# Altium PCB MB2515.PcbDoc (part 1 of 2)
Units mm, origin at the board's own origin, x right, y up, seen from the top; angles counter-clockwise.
Board outline 43 x 51.45 mm, 4 copper layers (Top Layer, Internal 1, Internal 2, Bottom Layer), stack 1.565 mm thick; 100 components, 89 nets, 374 pads, 852 vias.
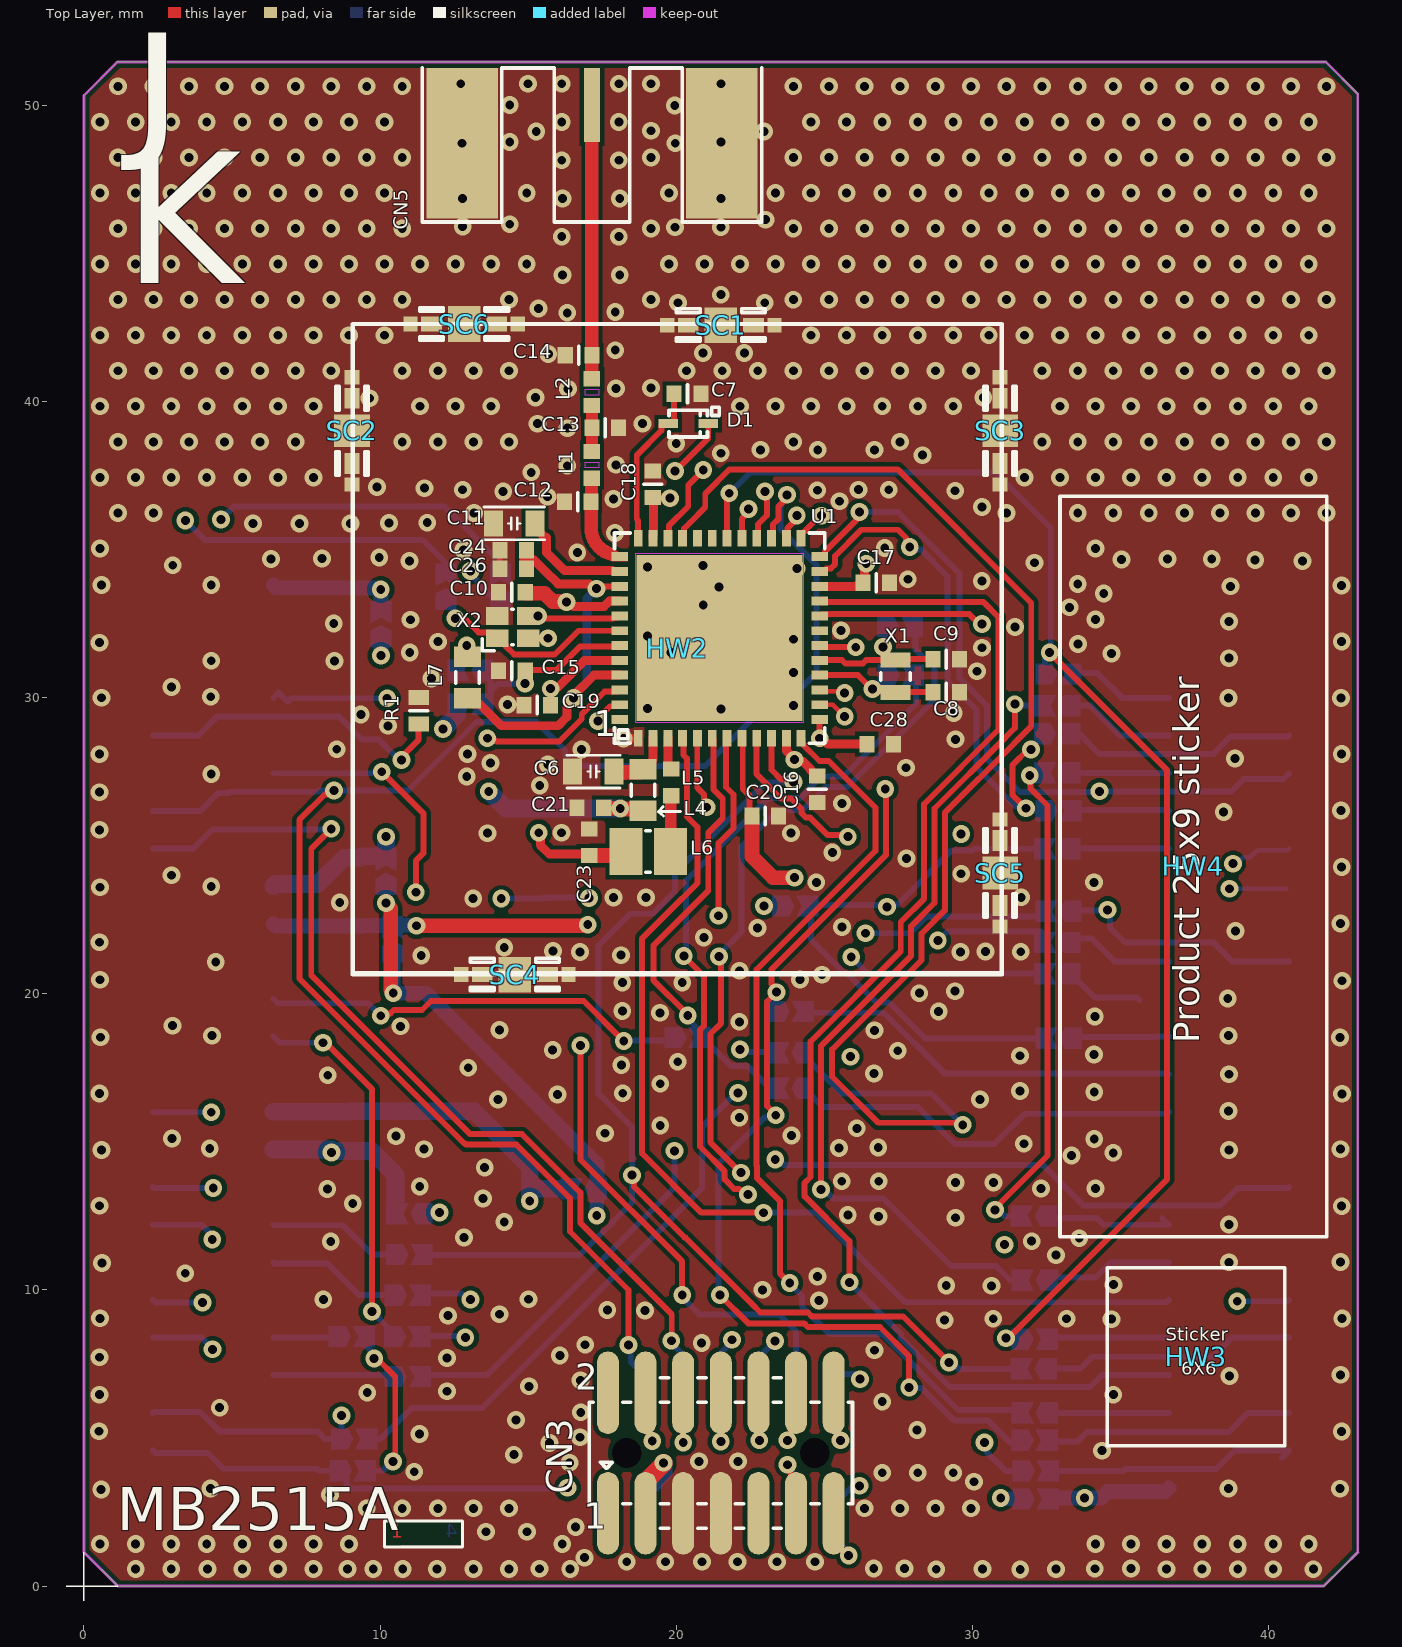
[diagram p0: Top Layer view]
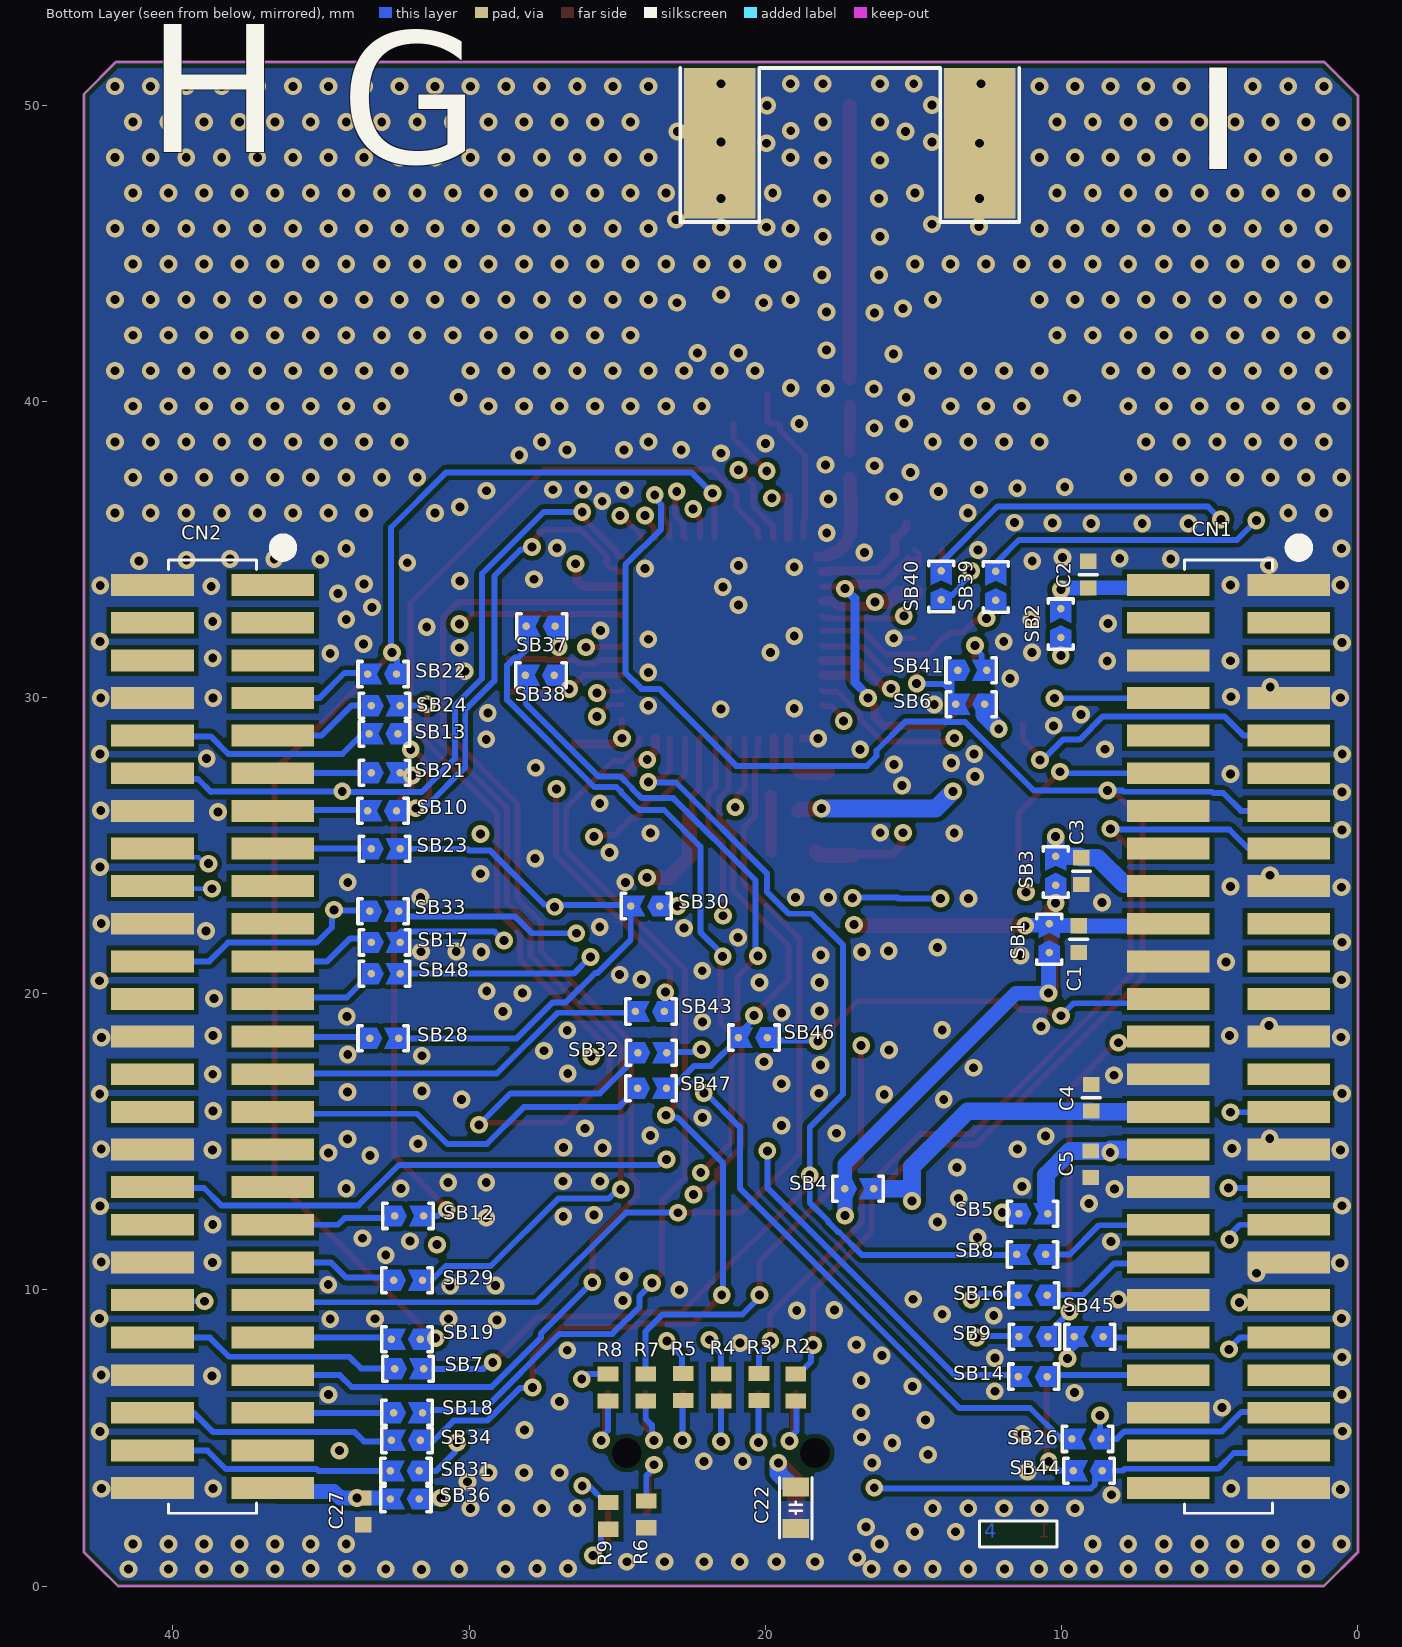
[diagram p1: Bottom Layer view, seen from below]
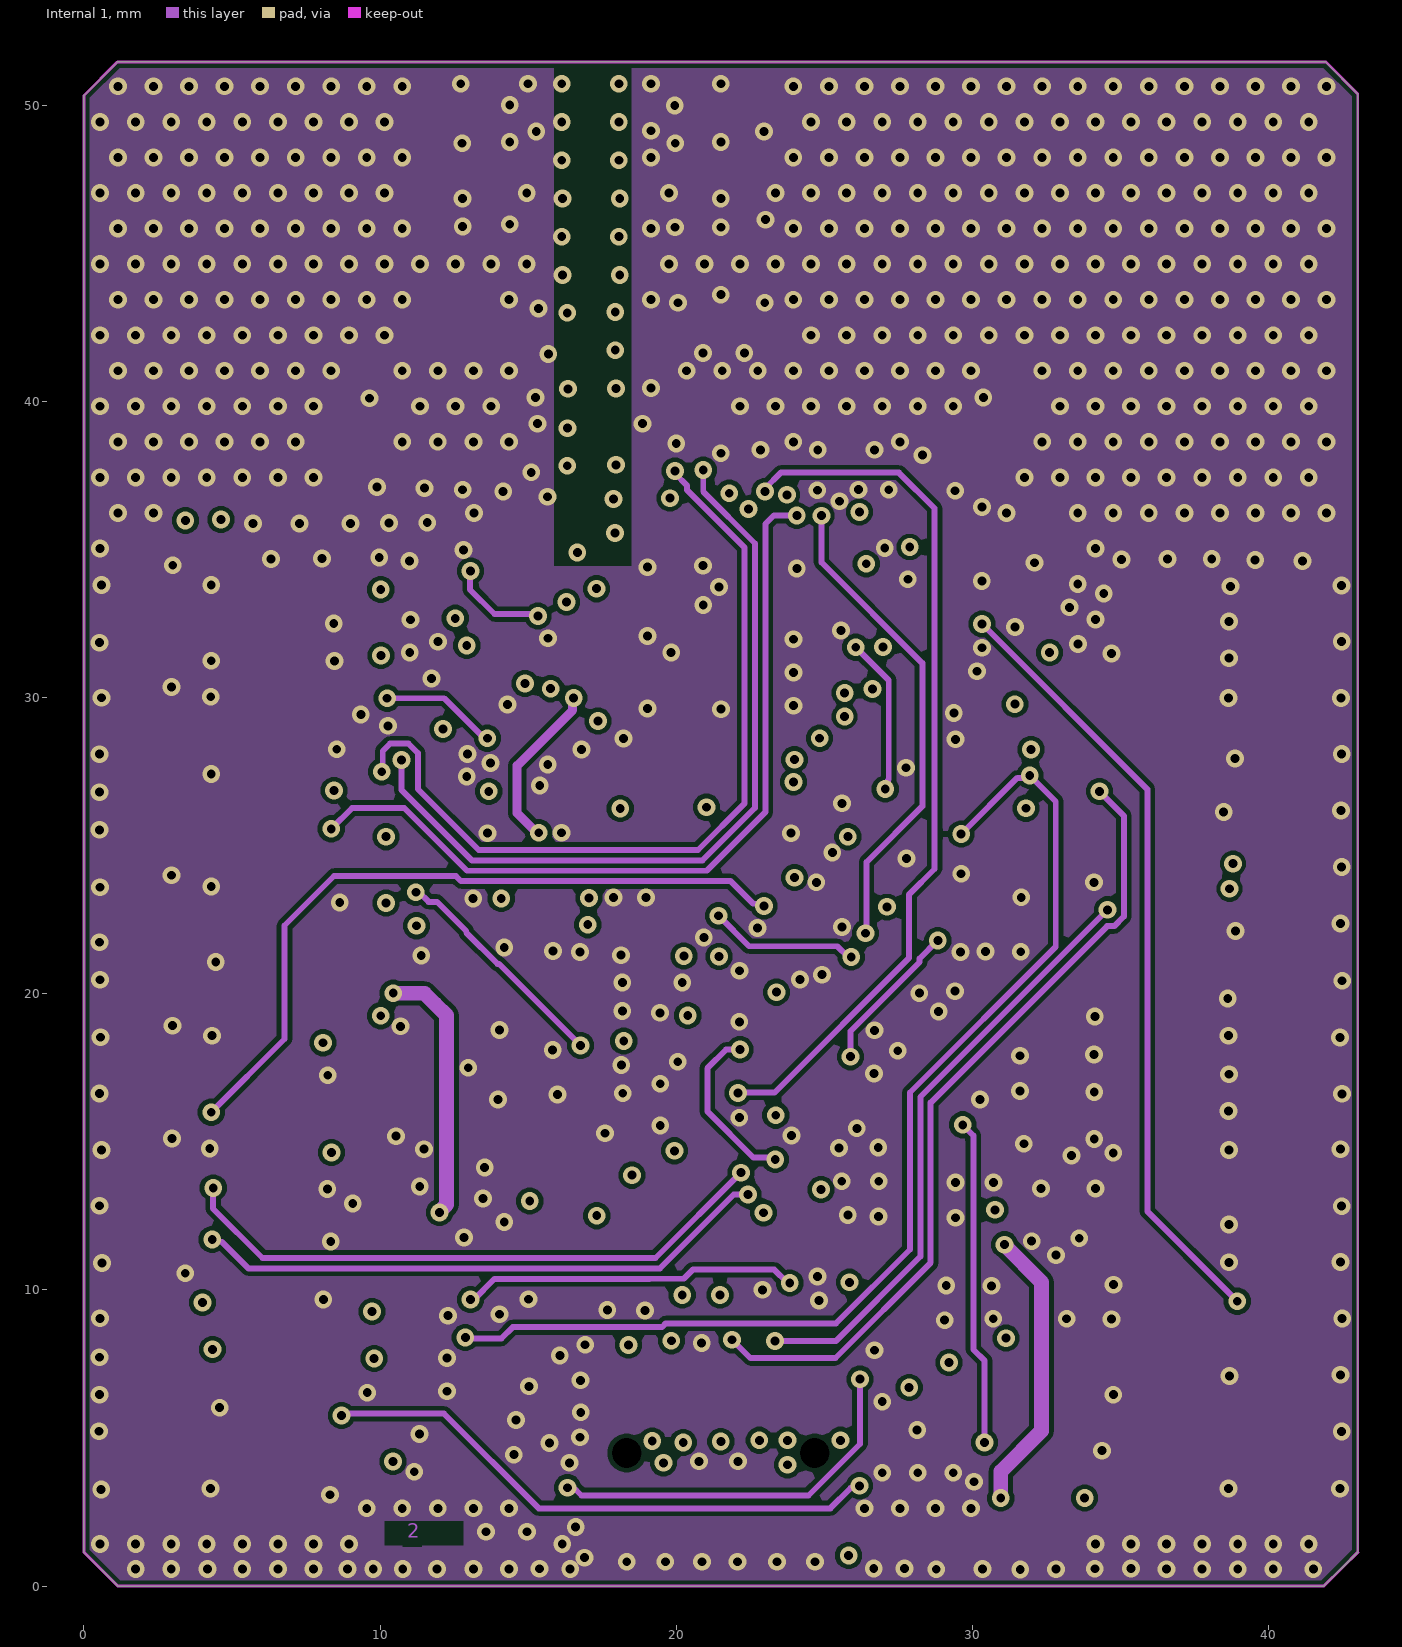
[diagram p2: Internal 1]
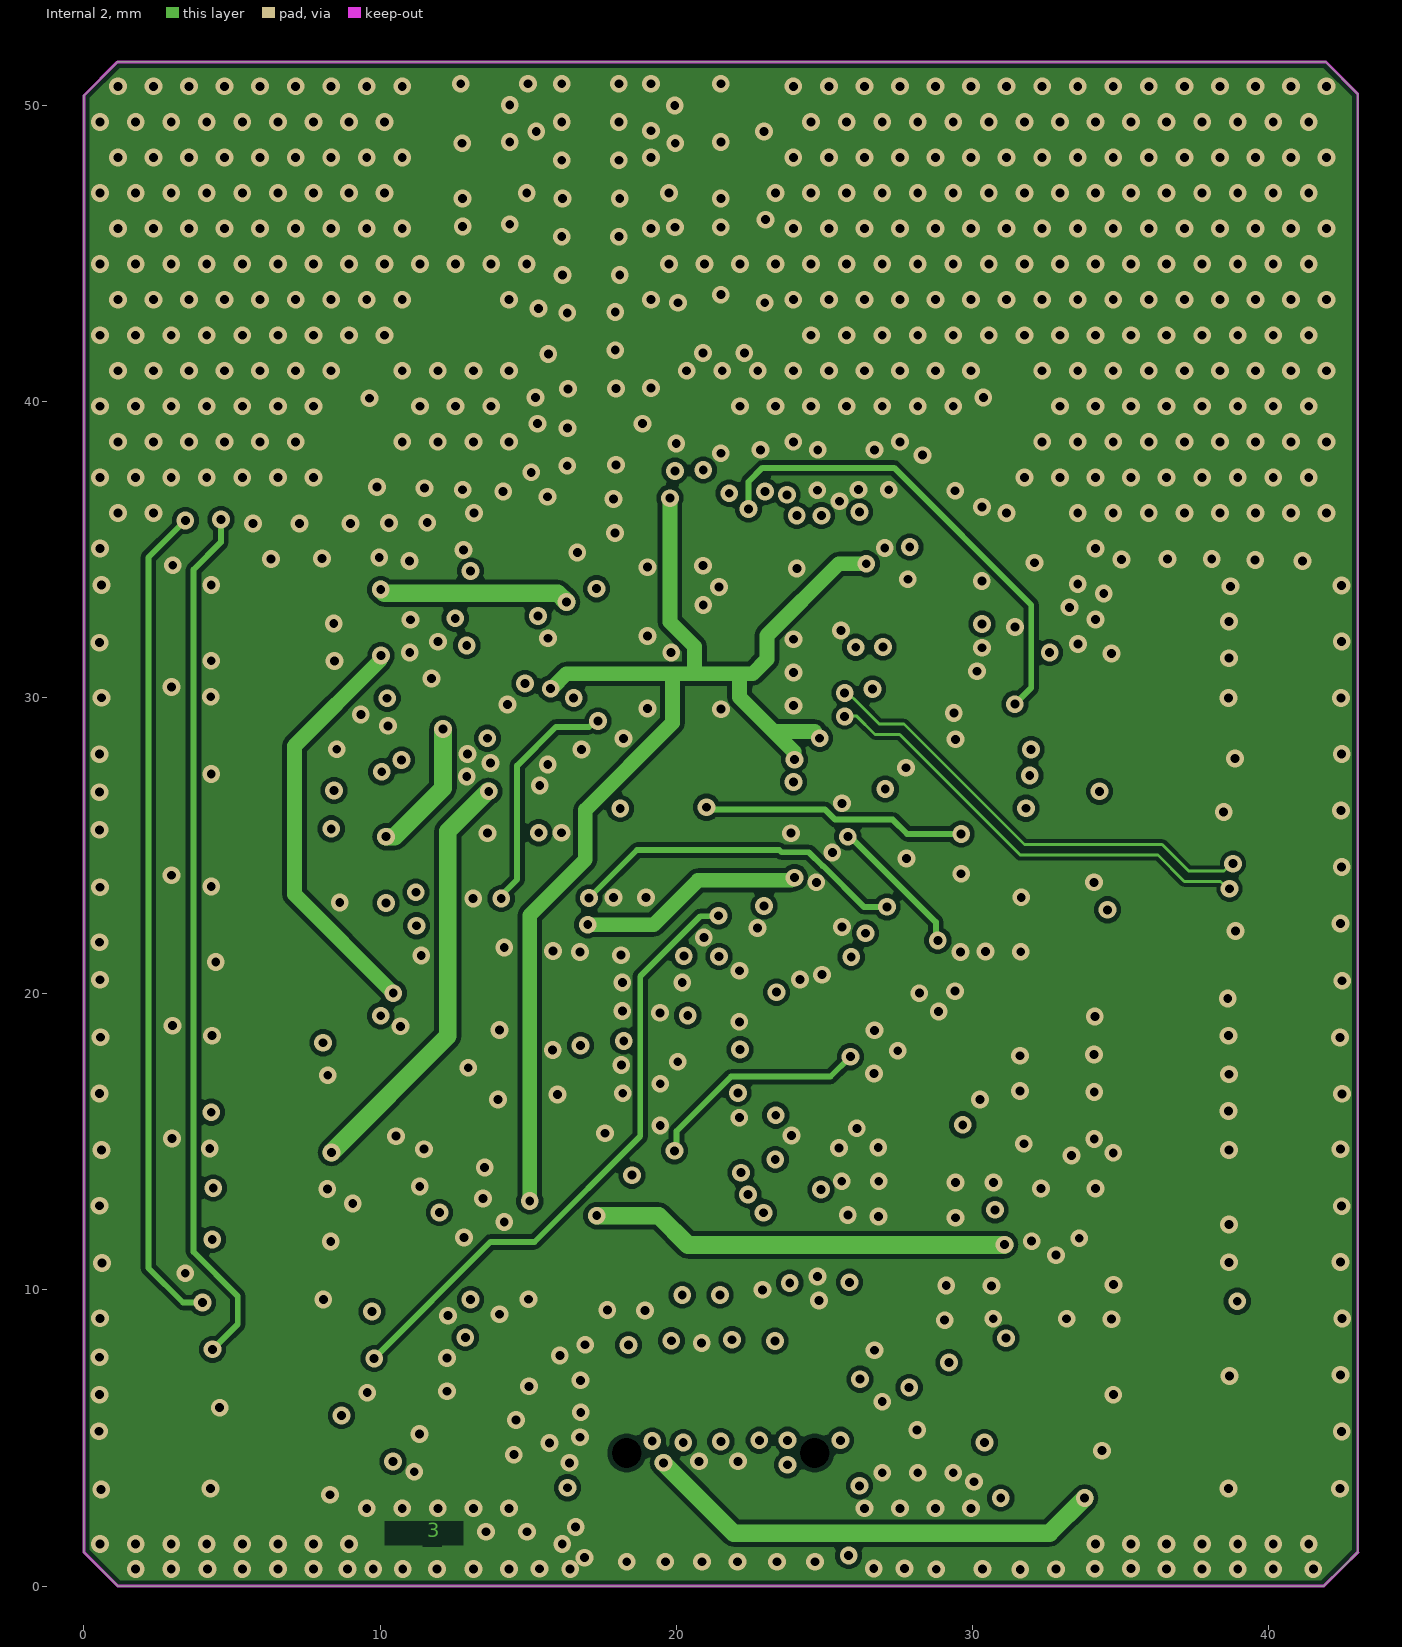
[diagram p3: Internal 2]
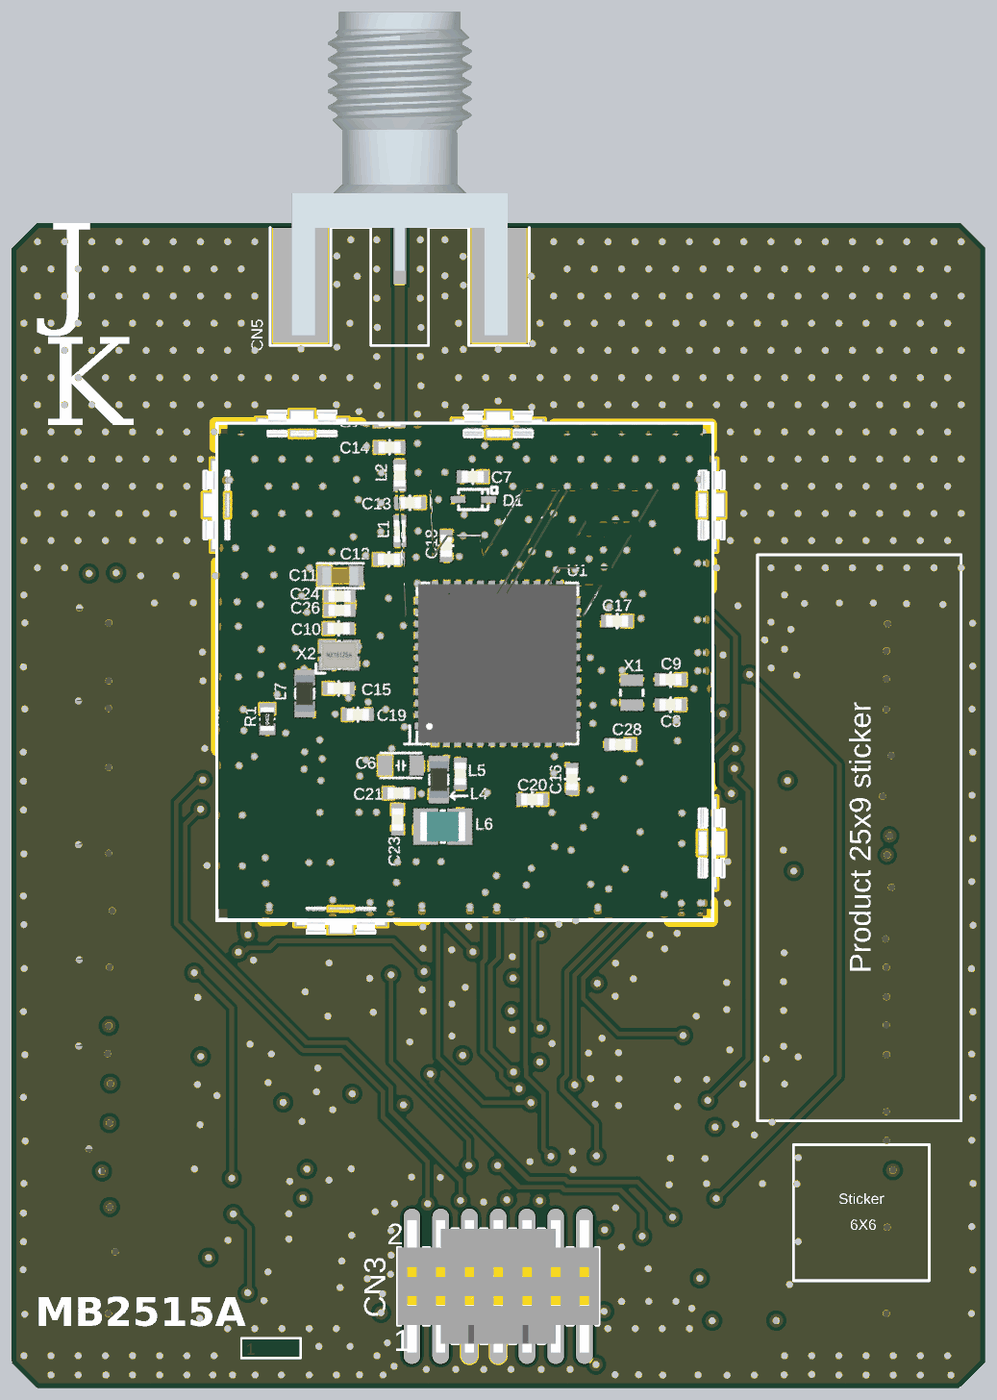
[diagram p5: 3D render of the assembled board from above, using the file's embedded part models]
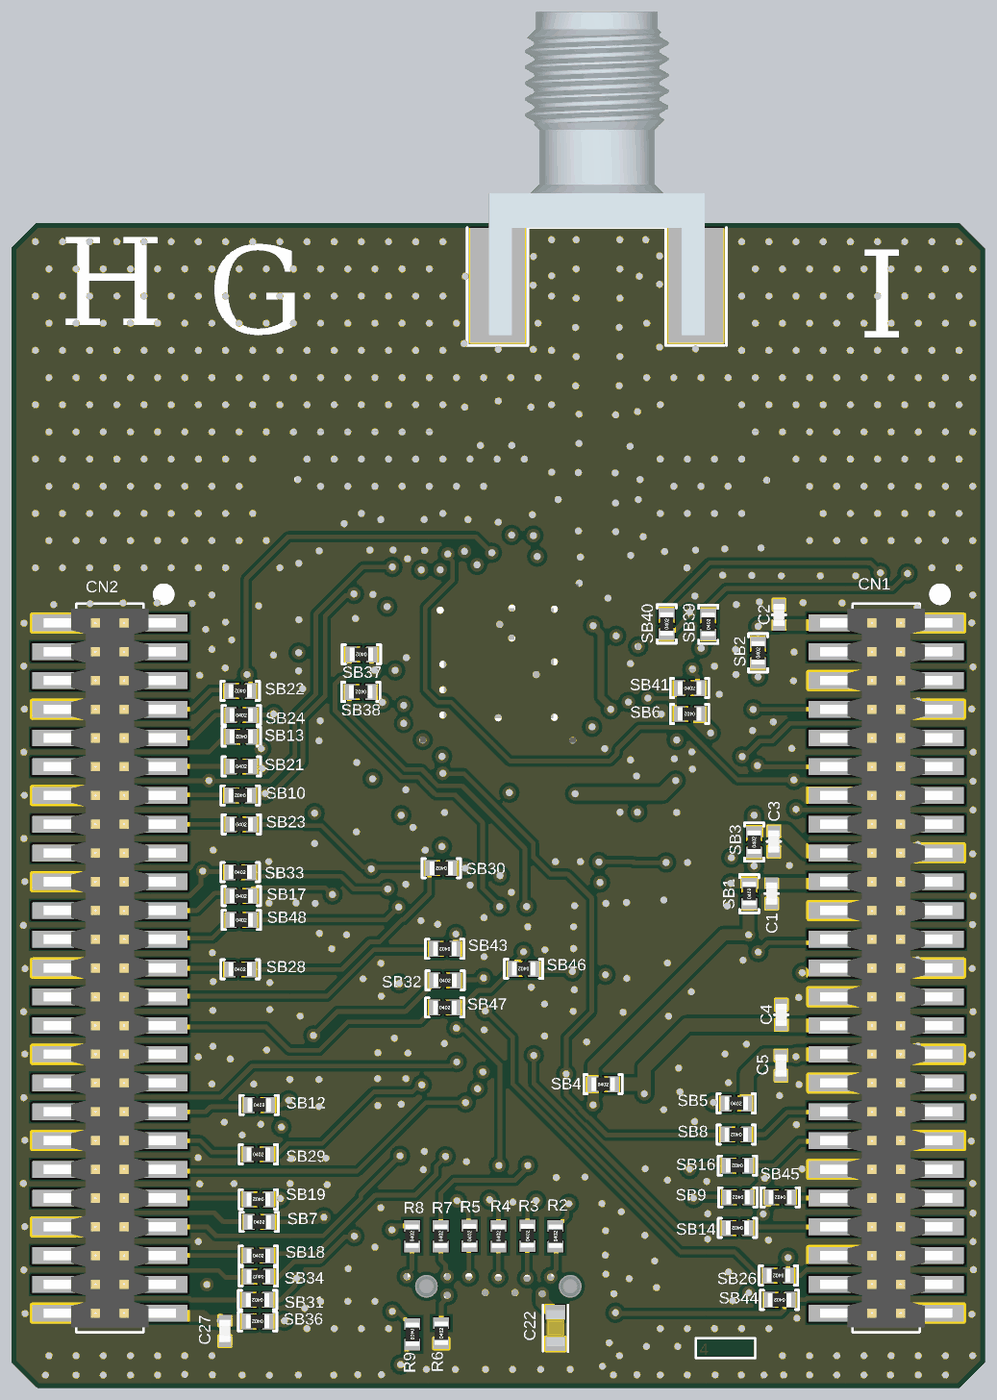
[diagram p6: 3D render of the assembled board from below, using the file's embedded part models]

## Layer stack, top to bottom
Top Solder: solder mask 0.0178, Solder Resist, Dk 4.2
Top Layer: signal copper 0.0406
Dielectric 1: prepreg 0.0762, FR-4, Dk 3.7
Internal 1: signal copper 0.0305
Dielectric 3: core 1.27, FR-4, Dk 4.5
Internal 2: signal copper 0.0305
Dielectric 2: prepreg 0.0762, FR-4, Dk 3.7
Bottom Layer: signal copper 0.0406
Bottom Solder: solder mask 0.0178, Solder Resist, Dk 4.2

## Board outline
0.001,1.143 0.001,50.3 0.001,50.324 1.132,51.455 41.913,51.455 43.001,50.367 43.001,39.986 43.002,1.145 41.852,0.005 1.139,0.005

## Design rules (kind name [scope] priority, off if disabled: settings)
Clearance Clearance_USB [InNetClass('DIFF90')] p1: gap=0.13 ignorepadtopadclearanceinfootprint=FALSE
Clearance RF [All vs (ObjectKind = 'Track') And (Net = 'NetC14_1') Or (Net = 'NetC13_2') Or (Net = 'NetC12_1')] p2: gap=0.13 ignorepadtopadclearanceinfootprint=FALSE
Clearance [All] p3: gap=0.15 ignorepadtopadclearanceinfootprint=FALSE
ComponentClearance [Not InComponent('HW2') vs Not InComponent('SC1') and InComponent('SC2') and InComponent('SC3') and InComponent('SC4') and InComponent('SC5')] p1: gap=0.2 collisioncheckmode=3 verticalgap=0.2 showdistances=FALSE
DiffPairsRouting [All] p1: maxlimit=0.254 minlimit=0.15 mostfreqgap=0.25 toplayer_prefgap=0.226 toplayer_minwidth=0.155 toplayer_maxwidth=0.226 toplayer_prefwidth=0.155 midlayer1_prefgap=0.15 midlayer1_minwidth=0.083 midlayer1_maxwidth=0.127 midlayer1_prefwidth=0.1 midlayer2_mingap=0.25 midlayer2_maxgap=0.25 midlayer2_minwidth=0.1 midlayer2_maxwidth=0.1 midlayer2_prefwidth=0.1 bottomlayer_prefgap=0.226 bottomlayer_minwidth=0.155 bottomlayer_maxwidth=0.226 bottomlayer_prefwidth=0.155 maxuncoupledlength=12.7
HoleSize [All] p1: absolutevalues=TRUE maxlimit=10 minlimit=0.025 maxpercent=80.000 minpercent=20.000
LayerPairs [All] p1 off: enforce=TRUE
MinimumSolderMaskSliver [All] p1 off: minsoldermaskwidth=0.1
PasteMaskExpansion [All] p1 off: expansion=0
PlaneConnect [All] p1: planeconnectstyle=Relief reliefexpansion=0.508 reliefentries=4 reliefconductorwidth=0.21 reliefairgap=0.21
PolygonConnect Path_RF [InNet('NetC12_2')] p1: connectstyle=Direct reliefconductorwidth=0.254 reliefentries=4 polygonreliefangle="90 Angle" airgapwidth=0.254
PolygonConnect PolygonConnect_via [IsVia] p2: connectstyle=Direct reliefconductorwidth=0.254 reliefentries=4 polygonreliefangle="90 Angle" airgapwidth=0.254
PolygonConnect General [All] p3: connectstyle=Direct reliefconductorwidth=0.2 reliefentries=4 polygonreliefangle="90 Angle" airgapwidth=0.2
RoutingVias [All] p1: holewidth=0.3 width=0.8 viastyle="Through Hole" minholewidth=0.2 minwidth=0.5 maxholewidth=3.5 maxwidth=6.5
SilkToSilkClearance [All] p1 off: silktosilkclearance=0.2
SilkToSolderMaskClearance [IsPad] p1 off: minsilkscreentomaskgap=0.2 clearancetoexposedcopper=TRUE
SolderMaskExpansion [All] p1: expansion=0.102 istentingtop=FALSE
Width [All] p1: maxlimit=6 minlimit=0.15 preferedwidth=0.254 toplayer_prefwidth=0.2 midlayer1_minwidth=0.2 midlayer1_maxwidth=1 midlayer2_minwidth=0.2 midlayer2_maxwidth=1 bottomlayer_prefwidth=0.2 minimp=50.000000 maximp=50.000000 favimp=50.000000
21 further rules are at their usual default settings.

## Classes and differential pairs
net class DIFF90: USB_FS_N USB_FS_P
net class VDD4: VDD4
net class SWDIO: GPIO5/JTMS/SWDIO
net class SWCLK: GPIO6/JTCK/SWCLK
net class X2: NetSB39_1 NetSB40_1 OSC_IN OSC_OUT
net class X1: GPIO15/OSC32_IN GPIO16/OSC32_OUT NetC8_1 NetC9_2
net class DC/DC: NetC23_2 NetL5_2 NetL7_2
component class "STM32 microcontroller I/Os & Clock": C1 C2 C3 C4 C5 C7 C8 C9 C27 CN1 CN2 D1 R1 SB1 SB2 SB3 SB4 SB5 SB7 SB8 SB9 SB10 SB12 SB13 SB14 SB16 SB17 SB18 SB19 SB21 SB22 SB23 SB24 SB26 SB28 SB29 SB30 SB31 SB32 SB33 SB34 SB36 SB36: SB37 SB38 SB39 SB40 SB43 SB44 SB45 SB46 SB47 SB48 U1 X1 X2
component class "RF & Power Management Schematic": C6 C10 C11 C12 C13 C14 C15 C16 C17 C18 C19 C20 C21 C22 C23 C24 C26 C28 CN3 CN5 HW2 L1 L2 L4 L5 L6 L7 R2 R3 R4 R5 R6 R7 R8 R9 SB6 SB41 SC1 SC2 SC3 SC4 SC5 SC6
component class Project_Overview: HW3 HW4
differential pair USB_FS: +USB_FS_P -USB_FS_N

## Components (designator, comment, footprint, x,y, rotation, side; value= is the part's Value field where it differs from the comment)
C1 "Capacitor" C0402 9.422,21.843 r90 bottom value=1uF
C2 "Capacitor" C0402 9.1,34.15 r270 bottom value=1uF
C3 "Capacitor" C0402 9.329,24.142 r90 bottom value=1uF
C4 "Capacitor" C0402 9.001,16.486 r270 bottom value=1uF
C5 "Capacitor" C0402 9.013,14.247 r90 bottom value=1uF
C6 "Capacitor" C0603_H0P8 17.2,27.5 r180 top value=10µF
C7 "Capacitor" C0402 20.375,40.25 r180 top value=100nF
C8 "Capacitor" C0402 29.11,30.18 r0 top value=6pF
C9 "Capacitor" C0402 29.113,31.295 r180 top value=6pF
C10 "Capacitor" C0402 14.45,33.55 r180 top value=100nF
C11 "Capacitor" C0603 14.525,35.875 r0 top value=470nF
C12 "Capacitor" C0402 16.671,36.605 r180 top value=1.5pF
C13 "Capacitor" C0402 17.6,39.1 r180 top value=1.8pF
C14 "Capacitor" C0402 16.7,41.55 r180 top value=1pF
C15 "Capacitor" C0402 14.45,30.903 r180 top value=100nF
C16 "Capacitor" C0402 24.757,26.9 r270 top value=100nF
C17 "Capacitor" C0402 26.75,33.875 r0 top value=100nF
C18 "Capacitor" C0402 19.2,37.2 r90 top value=100nF
C19 "Capacitor" C0402 15.3,29.745 r180 top value=100nF
C20 "Capacitor" C0402 23,26 r180 top value=1uF
C21 "Capacitor" C0402 17.1,26.275 r180 top value=1uF
C22 "Capacitor" C0603 18.975,2.65 r90 bottom value=1uF
C23 "Capacitor" C0402 17.053,25.116 r270 top value=4.7uF
C24 "Capacitor" C0402 14.492,34.976 r180 top value=100nF
C26 "Capacitor" C0402 14.492,34.351 r180 top value=100nF
C27 "Capacitor" C0402 33.575,2.525 r90 bottom value=1uF
C28 "Capacitor" C0402 26.884,28.426 r0 top value=100nF
CN1 "FTSH-125-02-L-DV" FTSH-125-02-L-DV 4.367,18.553 r180 bottom locked
CN2 "FTSH-125-02-L-DV" FTSH-125-02-L-DV 38.657,18.553 r180 bottom locked
CN3 "Header 7x2" CON_SAMTEC_FTSH-107-01-L-DV-K-A 21.5,4.497 r0 top
CN5 "SMA-J-P-H-ST-EM1" 142-0701-851 17.15,48.75 r0 top value=Jack_SMA_142-0701-851
D1 "SCHOTTKY_1A_2K" DIO_SOD523_1A_2K 20.4,39.244 r0 top value=BAT54KFILM
HW2 "Shield Cover" SHIELD_WURTH_36003200_21P8X21P8 20.027,31.657 r0 top locked value=36003200
HW3 "STICKER_ES" STICKER_ES_6X6 37.542,7.747 r0 top value=N/A
HW4 "STICKER_PRODUCT" STICKER_PRODUCT_25X9 37.45,24.3 r90 top value=N/A
L1 "Inductor" C0402 17.15,37.85 r90 top value=3.3nH
L2 "Inductor" C0402 17.145,40.308 r90 top value=3.3nH
L4 "Inductor" IND_0603_H0P8 18.875,26.875 r270 top value="47R @ 100MHz"
L5 "Inductor" C0402 19.824,27.133 r270 top value=10nH
L6 "Inductor" L0805_H0P9 19.05,24.8 r180 top value=2.2uH
L7 "Inductor" IND_0603_H0P8 12.95,30.675 r90 top value="47R @ 100MHz"
R1 "Resistor" R0402 11.3,29.55 r90 top value=100K
R2 "Resistor" R0402 18.975,6.708 r90 bottom value=47R
R3 "Resistor" R0402 20.211,6.726 r90 bottom value=47R
R4 "Resistor" R0402 21.49,6.708 r90 bottom value=47R
R5 "Resistor" R0402 22.77,6.726 r90 bottom value=47R
R6 "Resistor" R0402 24.018,2.425 r90 bottom value=47R
R7 "Resistor" R0402 24.04,6.708 r90 bottom value=47R
R8 "Resistor" R0402 25.31,6.708 r90 bottom value=47R
R9 "Resistor" R0402 25.3,2.375 r270 bottom value=47R
SB1 "SB_ON" SOLDER-BRIDGE_R0402-0R 10.413,21.839 r90 bottom
SB2 "SB_ON" SOLDER-BRIDGE_R0402-0R 10.025,32.475 r90 bottom
SB3 "SB_ON" SOLDER-BRIDGE_R0402-0R 10.2,24.113 r90 bottom
SB4 "SB_ON" SOLDER-BRIDGE_R0402-0R 16.87,13.419 r180 bottom
SB5 "SB_ON" SOLDER-BRIDGE_R0402-0R 10.988,12.574 r180 bottom
SB6 "SB_ON" SOLDER-BRIDGE_R0402-0R 13.05,29.775 r0 bottom
SB7 "SB_ON" SOLDER-BRIDGE_R0402-0R 32.059,7.339 r180 bottom
SB8 "SB_ON" SOLDER-BRIDGE_R0402-0R 10.988,11.199 r0 bottom
SB9 "SB_ON" SOLDER-BRIDGE_R0402-0R 10.914,8.425 r0 bottom
SB10 "SB_ON" SOLDER-BRIDGE_R0402-0R 32.9,26.173 r0 bottom
SB12 "SB_ON" SOLDER-BRIDGE_R0402-0R 32.059,12.5 r180 bottom
SB13 "SB_ON" SOLDER-BRIDGE_R0402-0R 32.851,28.775 r0 bottom
SB14 "SB_ON" SOLDER-BRIDGE_R0402-0R 10.938,7.076 r0 bottom
SB16 "SB_ON" SOLDER-BRIDGE_R0402-0R 10.938,9.825 r0 bottom
SB17 "SB_ON" SOLDER-BRIDGE_R0402-0R 32.851,21.732 r180 bottom
SB18 "SB_ON" SOLDER-BRIDGE_R0402-0R 32.097,5.853 r180 bottom
SB19 "SB_ON" SOLDER-BRIDGE_R0402-0R 32.097,8.336 r0 bottom
SB21 "SB_ON" SOLDER-BRIDGE_R0402-0R 32.851,27.458 r180 bottom
SB22 "SB_ON" SOLDER-BRIDGE_R0402-0R 32.9,30.79 r0 bottom
SB23 "SB_ON" SOLDER-BRIDGE_R0402-0R 32.851,24.894 r180 bottom
SB24 "SB_ON" SOLDER-BRIDGE_R0402-0R 32.851,29.725 r180 bottom
SB26 "SB_ON" SOLDER-BRIDGE_R0402-0R 9.126,4.973 r0 bottom
SB28 "SB_ON" SOLDER-BRIDGE_R0402-0R 32.9,18.495 r180 bottom
SB29 "SB_ON" SOLDER-BRIDGE_R0402-0R 32.097,10.325 r180 bottom
SB30 "SB_ON" SOLDER-BRIDGE_R0402-0R 24.018,22.96 r0 bottom
SB31 "SB_ON" SOLDER-BRIDGE_R0402-0R 32.134,3.893 r0 bottom
SB32 "SB_ON" SOLDER-BRIDGE_R0402-0R 23.85,18.008 r180 bottom
SB33 "SB_ON" SOLDER-BRIDGE_R0402-0R 32.9,22.786 r180 bottom
SB34 "SB_ON" SOLDER-BRIDGE_R0402-0R 32.097,4.925 r0 bottom
SB36 "SB_ON" SOLDER-BRIDGE_R0402-0R 32.134,2.945 r0 bottom
SB37 "SB_ON" SOLDER-BRIDGE_R0402-0R 27.548,32.407 r0 bottom
SB38 "SB_ON" SOLDER-BRIDGE_R0402-0R 27.575,30.75 r0 bottom
SB39 "SB_ON" SOLDER-BRIDGE_R0402-0R 12.225,33.732 r90 bottom
SB40 "SB_ON" SOLDER-BRIDGE_R0402-0R 14.063,33.75 r90 bottom
SB41 "SB_ON" SOLDER-BRIDGE_R0402-0R 13.051,30.917 r180 bottom
SB43 "SB_ON" SOLDER-BRIDGE_R0402-0R 23.861,19.402 r0 bottom
SB44 "SB_ON" SOLDER-BRIDGE_R0402-0R 9.079,3.898 r0 bottom
SB45 "SB_ON" SOLDER-BRIDGE_R0402-0R 9.048,8.425 r0 bottom
SB46 "SB_ON" SOLDER-BRIDGE_R0402-0R 20.382,18.52 r0 bottom
SB47 "SB_ON" SOLDER-BRIDGE_R0402-0R 23.861,16.809 r180 bottom
SB48 "SB_ON" SOLDER-BRIDGE_R0402-0R 32.851,20.678 r180 bottom
SC1 "Shield-clip_S0951-46R" CLIP_HARWIN_S0951-46R 21.5,42.568 r180 top value=S0951-46R
SC2 "Shield-clip_S0951-46R" CLIP_HARWIN_S0951-46R 9.05,39 r270 top value=S0951-46R
SC3 "Shield-clip_S0951-46R" CLIP_HARWIN_S0951-46R 30.925,39 r90 top value=S0951-46R
SC4 "Shield-clip_S0951-46R" CLIP_HARWIN_S0951-46R 14.55,20.645 r180 top value=S0951-46R
SC5 "Shield-clip_S0951-46R" CLIP_HARWIN_S0951-46R 30.925,24.075 r270 top value=S0951-46R
SC6 "Shield-clip_S0951-46R" CLIP_HARWIN_S0951-46R 12.836,42.607 r180 top value=S0951-46R
U1 "IC_STM32WBA25CEU6" ICC_UFQFPN48-EPAD_7X7_H0P55_P050 21.461,32.003 r90 top locked value=STM32WBA25CEU6
X1 "XTAL_2_PINS" CRY_NX1610SE_2P 27.398,30.715 r270 top value=32.768kHz
X2 "XTAL_4_PINS" CRY_NX1612SA_4P 14.475,32.375 r0 top value=32MHz

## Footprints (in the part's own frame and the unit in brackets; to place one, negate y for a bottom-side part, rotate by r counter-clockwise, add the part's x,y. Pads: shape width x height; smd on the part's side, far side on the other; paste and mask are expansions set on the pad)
142-0701-851 [mm]
  rect 0.55x2.5 smd mask+0.05: 1(0,1.25)
  rect 2.413x5.08 smd mask+0.05: 2(4.381,-0.04) 3(-4.381,-0.04)
  rect 2.413x5.08 smd far side mask+0.05: 4(-4.381,-0.04) 5(4.381,-0.04)
  silkscreen extent -5.72,-2.7 5.72,2.5, body extent -4.8,-2.25 4.8,12.05, height 4.08
C0402 [mm]
  rect 0.51x0.56 smd mask+0.05: 1(-0.45,0) 2(0.45,0)
  silkscreen extent 0,-0.3 0,0.3, body extent -0.5,-0.3 0.5,0.3, height 0.4
C0603 [mm]
  rect 0.64x0.89 smd mask+0.05: 1(-0.7,0) 2(0.7,0)
  silkscreen extent -1.05,-0.55 1.02,0.55, body extent -0.9,-0.5 0.9,0.5, height 1.4
C0603_H0P8 [mm] "MCD-01540"
  rect 0.64x0.89 smd mask+0.05: 1(-0.7,0) 2(0.7,0)
  silkscreen extent -0.9,-0.55 0.9,0.55, body extent -0.9,-0.5 0.9,0.5, height 1
CLIP_HARWIN_S0951-46R [mm] "MCD-01587_CLIP-X1"
  rect 0.48x0.5 smd mask+0.1: 1(-1.81,0) 1(1.81,0)
  rect 0.7x0.5 smd mask+0.1: 1(-1.1,0) 1(1.1,0)
  rect 1.1x1.2 smd mask+0.1: 1(0,0)
  silkscreen extent -1.5,-0.55 1.5,0.55, body extent -2.05,-0.65 2.05,0.65, height 1.28
CON_SAMTEC_FTSH-107-01-L-DV-K-A [mm] "MCD-01959"
  oval 0.74x2.79 smd mask+0.05: 1(-3.81,-2.035) 2(-3.81,2.035) 3(-2.54,-2.035) 4(-2.54,2.035) 5(-1.27,-2.035) 6(-1.27,2.035) 7(0,-2.035) 8(0,2.035) 9(1.27,-2.035) 10(1.27,2.035) 11(2.54,-2.035) 12(2.54,2.035) 13(3.81,-2.035) 14(3.81,2.035)
  round 0 hole 1 unplated paste-2539.97 mask+0.05: NPTH1(-3.175,0) NPTH2(3.175,0)
  silkscreen extent -4.44,-2.54 4.44,2.54, body extent -4.44,-2.92 4.45,2.92, height 6.12
CRY_NX1610SE_2P [mm] "MCD-02291"
  rect 0.5x1 smd mask+0.05: 1(-0.55,0) 2(0.55,0)
  silkscreen extent -0.13,-0.5 0.13,0.5, body extent -0.8,-0.5 0.8,0.5, height 0.45
CRY_NX1612SA_4P [mm] "MCD-02262"
  rect 0.75x0.6 smd mask+0.038: 1(-0.525,-0.375) 2(0.525,-0.375) 3(0.525,0.375) 4(-0.525,0.375)
  silkscreen extent -1.02,-0.8 0.02,0.6, body extent -0.8,-0.6 0.8,0.6, height 0.51
DIO_SOD523_1A_2K [mm] "MCD-01677"
  rect 0.65x0.3 smd mask+0.05: 1(-0.675,0) 2(0.675,0)
  silkscreen extent -0.65,-0.45 1.05,0.55, body extent -0.85,-0.45 0.85,0.45, height 0.71
FTSH-125-02-L-DV [mil] "Header2x25 Reverse 1.27mm SAMTEC (FTSH-125-02-L-DV)"
  rect 110x29.02 smd: 1(80,600) 2(-80,600) 3(80,550) 4(-80,550) 5(80,500) 6(-80,500) 7(80,450) 8(-80,450) 9(80,400) 10(-80,400) 11(80,350) 12(-80,350) 13(80,300) 14(-80,300) 15(80,250) 16(-80,250) 17(80,200) 18(-80,200) 19(80,150) 20(-80,150) 21(80,100) 22(-80,100) 23(80,50) 24(-80,50) 25(80,0) 26(-80,0) 27(80,-50) 28(-80,-50) 29(80,-100) 30(-80,-100) 31(80,-150) 32(-80,-150) 33(80,-200) 34(-80,-200) 35(80,-250) 36(-80,-250) 37(80,-300) 38(-80,-300) 39(80,-350) 40(-80,-350) 41(80,-400) 42(-80,-400) 43(80,-450) 44(-80,-450) 45(80,-500) 46(-80,-500) 47(80,-550) 48(-80,-550) 49(80,-600) 50(-80,-600)
  silkscreen extent -58,-633 103,659, body extent -115,-625 115,625, height 190
ICC_UFQFPN48-EPAD_7X7_H0P55_P050 [mm] "MCD-01704"
  rect 0.55x0.3 smd mask+0.05: 1(-3.375,2.75) 2(-3.375,2.25) 3(-3.375,1.75) 4(-3.375,1.25) 5(-3.375,0.75) 6(-3.375,0.25) 7(-3.375,-0.25) 8(-3.375,-0.75) 9(-3.375,-1.25) 10(-3.375,-1.75) 11(-3.375,-2.25) 12(-3.375,-2.75) 25(3.375,-2.75) 26(3.375,-2.25) 27(3.375,-1.75) 28(3.375,-1.25) 29(3.375,-0.75) 30(3.375,-0.25) 31(3.375,0.25) 32(3.375,0.75) 33(3.375,1.25) 34(3.375,1.75) 35(3.375,2.25) 36(3.375,2.75)
  rect 0.3x0.55 smd mask+0.05: 13(-2.75,-3.375) 14(-2.25,-3.375) 15(-1.75,-3.375) 16(-1.25,-3.375) 17(-0.75,-3.375) 18(-0.25,-3.375) 19(0.25,-3.375) 20(0.75,-3.375) 21(1.25,-3.375) 22(1.75,-3.375) 23(2.25,-3.375) 24(2.75,-3.375) 37(2.75,3.375) 38(2.25,3.375) 39(1.75,3.375) 40(1.25,3.375) 41(0.75,3.375) 42(0.25,3.375) 43(-0.25,3.375) 44(-0.75,3.375) 45(-1.25,3.375) 46(-1.75,3.375) 47(-2.25,3.375) 48(-2.75,3.375)
  rect 5.6x5.6 smd paste-2539.97 mask+0.05: 49(0,0)
  silkscreen extent -3.55,-3.55 3.55,3.55, body extent -3.5,-3.5 3.5,3.5, height 0.65
IND_0603_H0P8 [mm]
  rect 0.7x0.9 smd mask+0.05: 1(-0.7,0) 2(0.7,0)
  silkscreen extent -0.2,-0.4 0.2,0.4, body extent -0.8,-0.4 0.8,0.4, height 0.8
L0805_H0P9 [mm]
  rect 1.1x1.6 smd mask+0.05: 1(-0.75,0) 2(0.75,0)
  silkscreen extent -0.08,-0.7 0.08,0.7, body extent -1.07,-0.7 1.07,0.7, height 1.2
R0402 [mm]
  rect 0.51x0.7 smd mask+0.05: 1(-0.45,0) 2(0.45,0)
  silkscreen extent 0,-0.3 0,0.3, body extent -0.52,-0.3 0.52,0.3, height 0.4
SHIELD_WURTH_36003200_21P8X21P8 [mm] "MCD-04686"
  silkscreen extent -10.95,-10.95 10.95,10.95, body extent -10.9,-10.9 10.9,10.9, height 2.3
SOLDER-BRIDGE_R0402-0R [mil] "MCD-01619"
  round 10 smd paste-393.7: 1(-17.72,0) 2(20.67,0)
  Top Layer region: -30.51,-13.78 -30.51,13.78 -8.37,13.78 -1.48,0 -8.37,-13.78
  Top Layer region: 1.48,13.78 8.37,0 1.48,-13.78 30.51,-13.78 30.51,13.78
  silkscreen extent -33,-17 33,17, body extent -20,-12 20,12, height 14
STICKER_ES_6X6 [mm] "Sticker to mention board QR code 8X8"
  silkscreen extent -3,-3 3,3
STICKER_PRODUCT_25X9 [mm] "Sticker to mention board CPN code"
  silkscreen extent -12.5,-4.5 12.5,4.5

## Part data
C1 C2 C3 C4 C5 C20 C21 C27: library part MCD-01722, "Capacitor, MLCC, 1uF, 10V, X5R, +/-10%, 0402, T=0.5mm", Manufacturer=YAGEO, Manufacturer_Part_Number=CC0402KRX5R6BB105, Package=0402
C6: library part MCD-02733, "Capacitor, MLCC, 10uF, 10V, X6S, +/-20%, 0603, T=1mm", Manufacturer=MURATA, Manufacturer_Part_Number=GRM188C81A106MA73, Package=0603
C7 C10 C15 C16 C17 C18 C19 C24 C26 C28: library part MCD-00006, "Capacitor, MLCC, 100nF, 16V, X7R, +/-10%, 0402, T=0.5mm", Alternate_Manufacturer=MURATA, Alternate_Manufacturer_Part_Number=GCM155R71C104KA55D, Manufacturer=YAGEO, Manufacturer_Part_Number=CC0402KRX7R7BB104, Package=C0402
C8 C9: library part MCD-03185, "Capacitor, MLCC, 6 pF, 50V, NPO, ±0,25pF, 0402, T=0.5mm", Manufacturer=MURATA, Manufacturer_Part_Number=GJM1555C1H6R0CB01, Package=0402
C11: library part MCD-01006, "Capacitor, MLCC, 470nF, 16V, X7R, +/-10%, 0603, T=0.8mm", Manufacturer=YAGEO, Manufacturer_Part_Number=CC0603KRX7R7BB474, Package=0603
C12: library part MCD-02994, "Capacitor, MLCC, 1.5pF, 50V, C0G, +/-0.25pF, 0402, T=0.5mm", Manufacturer=MURATA, Manufacturer_Part_Number=GRM1555C1H1R5CA01, Package=0402
C13: library part MCD-02995, "Capacitor, MLCC, 1.8pF, 50V, C0G, +/-0.25pF, 0402, T=0.5mm", Manufacturer=MURATA, Manufacturer_Part_Number=GRM1555C1H1R8CA01, Package=0402
C14: library part MCD-03045, "Capacitor, MLCC, 1.0pF, 50V, C0G, +/-0.25pF, 0402, T=0.5mm", Manufacturer=MURATA, Manufacturer_Part_Number=GRM1555C1H1R0CA01, Package=0402
C22: library part MCD-00010, "Capacitor, MLCC, 1uF, 16V, X5R, 10%, 0603, T=0,8mm", Manufacturer=YAGEO, Manufacturer_Part_Number=CC0603KRX5R7BB105, Package=C0603
C23: library part MCD-01356, "Capacitor, MLCC, 4.7uF, 6V3, X5R, +/-20%, 0402, T=0.5mm", Manufacturer=MURATA, Manufacturer_Part_Number=GRM155R60J475ME47, Package=0402
CN1 CN2: library part MCD-02746, "Header 25x2, 12.7mm, SMT,height 4.83mm", Manufacturer=SAMTEC
CN3: library part MCD-01531, "Header, 7x2, 1.27mm, VR, T=5.97mm, FTSH series STDC14 without Alignment Pin", Manufacturer=SAMTEC, Manufacturer_Part_Number=FTSH-107-01-L-DV-K
CN5: library part MCD-02072, "Jack_SMA, VR, PCB edge, 50R, T=7.92mm", Manufacturer=CINCH, Manufacturer_Part_Number=142-0701-851
D1: library part MCD-01677, "Small signal Schottky diodes", Manufacturer=STMICROELECTRONICS, Manufacturer_HQ_COO=EU, Manufacturer_Part_Number=BAT54KFILM, Package=SOD-523
HW2: library part MCD-04686, "RF Shield cover, 21.5x21.5x3.3mm", Manufacturer="WURTH ELEKTRONIK", Manufacturer_Part_Number=36003200
HW3: library part MCD-00234, "Sticker ES, 6x6mm", Manufacturer=N/A
HW4: library part MCD-00547, "Sticker product, 25x9mm", Manufacturer=N/A, Manufacturer_HQ_COO=Unknown
L1 L2: library part MCD-03001, "Inductor, 3.3nH, +/-0.3nH, 800 mA, 0.125Ohm, 0402, T=0.5mm", Manufacturer=MURATA, Manufacturer_Part_Number=LQG15HS3N3S02, Package=0402
L4 L7: library part MCD-03831, "Ferrite bead, 47R @ 100MHz, +/-25%, 3.5A, 0R02, 0603, T=0.8mm", Manufacturer="TAIYO YUDEN", Manufacturer_Part_Number=LSMGA160808T470RG, Package=0603
L5: library part MCD-03035, "Inductor, 10nH, +/-2%, 500 mA, 0.26Ohm, 0402, T=0.5mm", Manufacturer=MURATA, Manufacturer_Part_Number=LQG15HS10NJ02D, Package=0402
L6: library part MCD-03791, "Inductor, 2.2uH, +/-20%, 1.8A, 0R138, 0805, T=0.8mm", Manufacturer=MURATA, Manufacturer_Part_Number=DFE21CCN2R2MELL, Package=0805
R1: library part MCD-00059, "Resistor, 100K, 0402, +/-1%, 1/16W", Manufacturer=YAGEO, Manufacturer_Part_Number=RC0402FR-07100KL, Package=0402
R2 R3 R4 R5 R6 R7 R8 R9: library part MCD-00481, "Resistor,47R,0402,1%,1/16W", Manufacturer=YAGEO, Manufacturer_Part_Number=RC0402FR-0747RL, Package=R0402
SB1 SB2 SB3 SB4 SB5 SB6 SB7 SB8 SB9 SB10 SB12 SB13 SB14 SB16 SB17 SB18 SB19 SB21 SB22 SB23 SB24 SB26 SB28 SB29 SB30 SB31 SB32 SB33 SB34 SB36 SB37 SB38 SB39 SB40 SB41 SB43 SB44 SB45 SB46 SB47 SB48: library part MCD-01618, "Solder Bridge 0402 ON", Manufacturer=YAGEO, Manufacturer_Part_Number=RC0402JR-070RL, Package=SB0402
SC1 SC2 SC3 SC4 SC5 SC6: library part MCD-01587, "shield clip Harwin S0951-46R to fix RF shielded cavity", Manufacturer=HARWIN, Manufacturer_Part_Number=S0951-46R
U1: library part MCD-04232, "MCU, ARM Cortex-M33 32-bit, 512KB Flash, 96KB RAM, Crypto", Manufacturer=STMICROELECTRONICS, Manufacturer_Part_Number=STM32WBA25CEU6, Package=UFQFPN48
X1: library part MCD-02579, "Crystal, 32.768kHz, 6pF, +/-20ppm, 70KR, 1.6x1mm", Manufacturer=NDK, Manufacturer_Part_Number=NX1610SE-32.768KHZ-EXS00A-MU01501, Package=1.6x1mm
X2: library part MCD-02578, "Crystal, 32MHz, 8pF, +/-10ppm, 40R, 1612(metric), T=0.3mm", Manufacturer=NDK, Manufacturer_Part_Number=NX1612SA-32MHZ-EXS00A-CS09166, Package=1612(metric)

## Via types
v1: diameter 0.6, hole 0.3, Top Layer to Bottom Layer, tented both sides, 852 vias

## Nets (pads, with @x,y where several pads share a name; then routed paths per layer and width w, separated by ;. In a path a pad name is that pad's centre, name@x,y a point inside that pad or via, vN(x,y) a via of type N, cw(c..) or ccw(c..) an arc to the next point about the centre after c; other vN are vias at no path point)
GND: C1.1 C2.1 C3.1 C4.1 C5.1 C6.2 C7.1 C8.2 C9.1 C10.2 C11.1 C12.2 C13.1 C14.2 C15.2 C16.2 C17.2 C18.2 C19.2 C20.1 C21.2 C22.1 C23.1 C24.2 C26.2 C27.1 C28.2 CN1.1 CN1.6 CN1.7 CN1.14 CN1.17 CN1.22 CN1.25 CN1.28 CN1.31 CN1.34 CN1.37 CN1.40 CN1.46 CN1.49 CN2.2 CN2.8 CN2.14 CN2.20 CN2.26 CN2.32 CN2.38 CN2.44 CN2.50 CN3.5 CN3.7 CN5.2 CN5.3 CN5.4 CN5.5 R1.2 R6.1 SC1.1 SC2.1 SC3.1 SC4.1 SC5.1 SC6.1 U1.1 U1.49 X2.2 X2.4 | length 1.8
  Top Layer w0.2: C26.2@14.032,34.583 14.032,34.361 C26.2@14.042,34.351 ; C26.2@14.037,34.583 14.037,34.971 C24.2@14.042,34.976 ; X2.2@15,32 v1(15.664,32) ; v1(18.215,28.616) v1@18.222,28.622 ; U1.1@18.705,28.622 U1.1@18.711,28.628
  Top Layer w0.3: v1@18.222,28.622 U1.1@18.705,28.622
  other v1: 1.748,0.58 2.948,0.58 4.174,0.58 5.348,0.58 6.548,0.58 7.748,0.58 8.895,0.58 9.767,0.58 10.764,0.58 11.92,0.58 13.15,0.58 14.348,0.58 15.375,0.589 16.414,0.58 28.77,0.574 30.33,0.581 31.609,0.567 32.814,0.575 34.126,0.589 36.548,0.575 37.748,0.575 38.948,0.575 40.148,0.575 41.5,0.575 26.662,0.595 27.702,0.595 35.347,0.602 18.325,0.825 19.626,0.825 20.864,0.825 22.064,0.825 23.4,0.825 24.675,0.825 16.9,0.964 0.548,1.43 1.748,1.43 2.948,1.43 4.148,1.43 5.348,1.43 6.548,1.43 7.748,1.43 8.948,1.43 16.148,1.43 34.148,1.43 35.348,1.43 36.548,1.43 37.748,1.43 38.948,1.43 40.148,1.43 41.348,1.43 13.575,1.84 14.955,1.84 16.6,2 9.548,2.63 10.748,2.63 11.948,2.63 13.148,2.63 14.348,2.63 26.348,2.63 27.548,2.63 28.748,2.63 29.948,2.63 8.311,3.088 0.582,3.262 4.275,3.295 38.638,3.298 42.405,3.292 30.05,3.525 26.948,3.83 28.148,3.83 29.348,3.83 11.152,3.864 16.393,4.166 20.763,4.216 22.076,4.216 14.513,4.441 34.372,4.575 15.716,4.835 16.748,5.03 11.331,5.134 0.512,5.23 42.457,5.221 28.127,5.272 14.59,5.613 16.77,5.871 4.583,6.028 26.948,6.23 0.53,6.466 34.75,6.466 9.564,6.535 12.253,6.583 15.028,6.748 16.761,6.95 38.675,7.1 42.415,7.135 12.253,7.699 0.53,7.728 16.066,7.788 26.685,7.967 16.921,8.151 20.854,8.21 29.056,8.981 34.688,9.015 0.547,9.043 30.697,9.03 33.174,9.03 42.475,9.04 12.291,9.132 14.027,9.181 17.67,9.32 18.941,9.303 24.81,9.649 8.083,9.681 15.009,9.688 22.903,10.006 29.11,10.154 30.638,10.141 34.755,10.179 24.767,10.452 3.42,10.565 0.607,10.912 38.657,10.933 42.415,10.945 32.814,11.175 8.331,11.635 31.993,11.649 33.601,11.745 12.833,11.773 38.653,12.209 14.191,12.296 29.421,12.439 26.819,12.479 25.787,12.535 42.457,12.829 0.53,12.841 9.076,12.917 13.474,13.085 8.218,13.41 32.303,13.426 34.148,13.43 11.336,13.489 29.421,13.632 30.706,13.632 25.581,13.669 26.832,13.669 13.529,14.137 33.338,14.536 34.748,14.63 0.59,14.725 38.657,14.725 11.484,14.754 42.415,14.754 4.25,14.775 25.49,14.797 26.816,14.812 31.728,14.936 34.105,15.092 2.974,15.112 10.537,15.191 23.882,15.215 17.595,15.292 26.091,15.456 19.456,15.549 22.125,15.818 38.638,16.042 13.976,16.428 30.249,16.428 15.987,16.6 0.53,16.628 18.189,16.641 42.468,16.621 34.105,16.682 31.595,16.719 19.456,16.962 8.23,17.25 38.653,17.284 26.669,17.309 12.973,17.503 18.141,17.593 20.045,17.705 31.595,17.907 34.095,17.95 27.472,18.076 15.824,18.096 0.565,18.533 42.405,18.524 4.325,18.585 38.638,18.585 26.685,18.765 14.028,18.776 10.69,18.9 2.994,18.922 22.126,19.052 34.126,19.227 19.445,19.355 28.853,19.402 18.175,19.413 38.613,19.837 28.201,20.019 29.404,20.087 18.175,20.377 20.196,20.377 42.475,20.438 0.547,20.473 24.177,20.48 24.917,20.645 22.131,20.778 4.45,21.075 11.386,21.292 18.129,21.303 16.744,21.408 29.588,21.408 30.432,21.425 31.624,21.419 15.837,21.447 14.188,21.557 0.53,21.737 20.926,21.896 38.876,22.118 22.742,22.215 25.587,22.251 42.415,22.368 8.638,23.082 13.14,23.213 17.873,23.251 18.976,23.251 31.64,23.255 0.547,23.594 4.3,23.618 24.725,23.76 34.095,23.76 2.961,24.002 29.613,24.051 42.457,24.274 27.768,24.567 25.264,24.763 13.624,25.421 23.872,25.421 16.12,25.435 0.53,25.533 38.475,26.138 42.433,26.185 25.587,26.428 0.53,26.803 15.39,27.033 12.923,27.337 4.3,27.418 27.751,27.629 15.659,27.742 13.721,27.792 38.859,27.941 0.525,28.087 12.95,28.096 42.457,28.089 16.798,28.244 8.537,28.251 29.421,28.587 10.267,29.043 9.348,29.425 29.366,29.475 21.503,29.605 19.025,29.625 23.949,29.725 14.299,29.768 0.59,29.992 38.638,29.98 42.433,29.987 4.284,30.025 2.954,30.352 11.736,30.644 23.949,30.84 30.143,30.885 4.3,31.239 8.458,31.235 38.653,31.327 34.688,31.485 11.001,31.515 19.824,31.515 30.32,31.679 33.56,31.809 0.53,31.851 11.95,31.884 42.457,31.887 23.949,31.965 19.025,32.075 25.561,32.261 31.428,32.375 8.433,32.502 38.653,32.562 11.023,32.624 34.148,32.63 33.273,33.043 20.907,33.125 34.425,33.511 21.435,33.732 38.702,33.753 42.45,33.782 0.59,33.8 4.3,33.793 33.548,33.83 30.311,33.937 27.812,33.99 24.066,34.357 19.025,34.4 3.001,34.463 20.9,34.45 32.087,34.549 10.988,34.605 41.138,34.605 39.538,34.646 6.313,34.676 35.027,34.656 36.575,34.676 38.071,34.676 8.036,34.689 9.97,34.724 16.657,34.89 12.817,34.982 0.548,35.03 34.148,35.03 27.035,35.051 17.925,35.55 5.711,35.875 7.275,35.875 9.001,35.875 10.302,35.891 11.59,35.902 1.148,36.23 2.348,36.23 13.164,36.228 31.148,36.23 33.548,36.23 34.748,36.23 35.948,36.23 37.148,36.23 38.348,36.23 39.548,36.23 40.748,36.23 41.948,36.23 30.313,36.429 25.506,36.625 17.873,36.7 15.651,36.777 14.152,36.95 29.41,36.98 12.787,37.012 24.757,36.996 27.17,37.012 26.145,37.016 11.497,37.067 9.893,37.108 0.548,37.43 1.748,37.43 2.948,37.43 4.148,37.43 5.348,37.43 6.548,37.43 7.748,37.43 31.748,37.43 32.948,37.43 34.148,37.43 35.348,37.43 36.548,37.43 37.748,37.43 38.948,37.43 40.148,37.43 41.348,37.43 15.1,37.6 16.315,37.822 17.964,37.854 28.308,38.18 21.5,38.245 22.839,38.361 24.772,38.361 26.689,38.361 19.995,38.571 1.148,38.63 2.348,38.63 3.548,38.63 4.748,38.63 5.948,38.63 7.148,38.63 10.748,38.63 11.948,38.63 13.148,38.63 14.348,38.63 23.948,38.63 27.548,38.63 32.348,38.63 33.548,38.63 34.748,38.63 35.948,38.63 37.148,38.63 38.348,38.63 39.548,38.63 40.748,38.63 41.948,38.63 16.321,39.091 15.315,39.244 18.856,39.244 0.548,39.83 1.748,39.83 2.948,39.83 4.148,39.83 5.348,39.83 6.548,39.83 7.748,39.83 11.348,39.83 12.548,39.83 13.748,39.83 22.148,39.83 23.348,39.83 24.548,39.83 25.748,39.83 26.948,39.83 28.148,39.83 29.348,39.83 32.948,39.83 34.148,39.83 35.348,39.83 36.548,39.83 37.748,39.83 38.948,39.83 40.148,39.83 41.348,39.83 9.644,40.1 15.241,40.129 30.361,40.129 16.337,40.42 17.964,40.434 19.142,40.45 1.148,41.03 2.348,41.03 3.548,41.03 4.748,41.03 5.948,41.03 7.148,41.03 8.348,41.03 10.748,41.03 11.948,41.03 13.148,41.03 14.348,41.03 20.348,41.03 21.548,41.03 22.748,41.03 23.948,41.03 25.148,41.03 26.348,41.03 27.548,41.03 28.748,41.03 29.948,41.03 32.348,41.03 33.548,41.03 34.748,41.03 35.948,41.03 37.148,41.03 38.348,41.03 39.548,41.03 40.748,41.03 41.948,41.03 15.677,41.591 20.902,41.631 22.293,41.631 17.935,41.724 0.548,42.23 1.748,42.23 2.948,42.23 4.148,42.23 5.348,42.23 6.548,42.23 7.748,42.23 8.948,42.23 10.148,42.23 24.548,42.23 25.748,42.23 26.948,42.23 28.148,42.23 29.348,42.23 30.548,42.23 31.748,42.23 32.948,42.23 34.148,42.23 35.348,42.23 36.548,42.23 37.748,42.23 38.948,42.23 40.148,42.23 41.348,42.23 16.315,42.984 17.935,43.014 15.35,43.129 20.057,43.325 22.983,43.325 1.148,43.43 2.348,43.43 3.548,43.43 4.748,43.43 5.948,43.43 7.148,43.43 8.348,43.43 9.548,43.43 10.748,43.43 14.348,43.43 19.148,43.43 23.948,43.43 25.148,43.43 26.348,43.43 27.548,43.43 28.748,43.43 29.948,43.43 31.148,43.43 32.348,43.43 33.548,43.43 34.748,43.43 35.948,43.43 37.148,43.43 38.348,43.43 39.548,43.43 40.748,43.43 41.948,43.43 21.5,43.597 16.159,44.266 18.087,44.266 0.548,44.63 1.748,44.63 2.948,44.63 4.148,44.63 5.348,44.63 6.548,44.63 7.748,44.63 8.948,44.63 10.148,44.63 11.348,44.63 12.548,44.63 13.748,44.63 14.948,44.63 19.748,44.63 20.948,44.63 22.148,44.63 23.348,44.63 24.548,44.63 25.748,44.63 26.948,44.63 28.148,44.63 29.348,44.63 30.548,44.63 31.748,44.63 32.948,44.63 34.148,44.63 35.348,44.63 36.548,44.63 37.748,44.63 38.948,44.63 40.148,44.63 41.348,44.63 16.13,45.556 18.058,45.556 1.148,45.83 2.348,45.83 3.548,45.83 4.748,45.83 5.948,45.83 7.148,45.83 8.348,45.83 9.548,45.83 10.748,45.83 19.148,45.83 23.948,45.83 25.148,45.83 26.348,45.83 27.548,45.83 28.748,45.83 29.948,45.83 31.148,45.83 32.348,45.83 33.548,45.83 34.748,45.83 35.948,45.83 37.148,45.83 38.348,45.83 39.548,45.83 40.748,45.83 41.948,45.83 19.956,45.875 21.5,45.875 12.786,45.897 14.375,45.975 23.012,46.129 12.777,46.846 16.159,46.846 18.087,46.846 21.5,46.846 0.548,47.03 1.748,47.03 2.948,47.03 4.148,47.03 5.348,47.03 6.548,47.03 7.748,47.03 8.948,47.03 10.148,47.03 14.948,47.03 19.748,47.03 23.348,47.03 24.548,47.03 25.748,47.03 26.948,47.03 28.148,47.03 29.348,47.03 30.548,47.03 31.748,47.03 32.948,47.03 34.148,47.03 35.348,47.03 36.548,47.03 37.748,47.03 38.948,47.03 40.148,47.03 41.348,47.03 16.13,48.136 18.058,48.136 1.148,48.23 2.348,48.23 3.548,48.23 4.748,48.23 5.948,48.23 7.148,48.23 8.348,48.23 9.548,48.23 10.748,48.23 19.148,48.23 23.948,48.23 25.148,48.23 26.348,48.23 27.548,48.23 28.748,48.23 29.948,48.23 31.148,48.23 32.348,48.23 33.548,48.23 34.748,48.23 35.948,48.23 37.148,48.23 38.348,48.23 39.548,48.23 40.748,48.23 41.948,48.23 12.769,48.71 19.96,48.71 14.375,48.75 21.5,48.75 15.27,49.104 22.96,49.104 19.142,49.129 0.548,49.43 1.748,49.43 2.948,49.43 4.148,49.43 5.348,49.43 6.548,49.43 7.748,49.43 8.948,49.43 10.148,49.43 16.13,49.426 18.058,49.426 24.548,49.43 25.748,49.43 26.948,49.43 28.148,49.43 29.348,49.43 30.548,49.43 31.748,49.43 32.948,49.43 34.148,49.43 35.348,49.43 36.548,49.43 37.748,49.43 38.948,49.43 40.148,49.43 41.348,49.43 19.944,49.98 14.375,50 1.148,50.63 2.348,50.63 3.548,50.63 4.748,50.63 5.948,50.63 7.148,50.63 8.348,50.63 9.548,50.63 10.748,50.63 23.948,50.63 25.148,50.63 26.348,50.63 27.548,50.63 28.748,50.63 29.948,50.63 31.148,50.63 32.348,50.63 33.548,50.63 34.748,50.63 35.948,50.63 37.148,50.63 38.348,50.63 39.548,50.63 40.748,50.63 41.948,50.63 12.72,50.716 14.988,50.716 16.13,50.716 18.058,50.716 19.145,50.716 21.5,50.716
GPIO3/BOOT0: CN1.9 R1.1 U1.34 | length 40.3
  Top Layer w0.2: v1(10.726,27.894) 10.726,28.003 11.3,28.577 R1.1@11.3,29.1 ; U1.34@19.711,35.378 19.747,35.414 19.747,35.793 20.4,36.447 20.4,37.168 v1(20.907,37.675)
  Internal 1 w0.2: v1(10.726,27.894) 10.726,26.872 13.097,24.501 20.882,24.501 22.654,26.273 22.654,35.2 20.907,36.947 v1(20.907,37.675)
  Bottom Layer w0.2: CN1.9@2.335,28.713 3.854,28.713 4.504,29.363 8.604,29.363 9.39,28.577 9.955,28.577 10.637,27.894 v1(10.726,27.894)
GPIO5/JTMS/SWDIO: CN1.13 R2.2 U1.27 | length 60.1
  Top Layer w0.2: v1(8.445,26.863) 8.34,26.863 8.202,26.725 8.132,26.725 7.275,25.868 7.275,20.513 12.844,14.944 12.858,14.944 12.892,14.91 14.598,14.91 16.407,13.1 16.407,11.975 18.384,9.998 v1(18.384,8.141) ; U1.27@23.211,35.378 23.256,35.423 23.256,35.838 23.45,36.032 23.45,36.453 23.733,36.735 v1(23.733,36.841)
  Bottom Layer w0.2: CN1.13@2.335,26.173 3.939,26.173 4.541,26.775 4.875,26.775 4.919,26.82 7.902,26.82 7.945,26.863 v1(8.445,26.863) 10.939,26.863 13.251,29.175 13.929,29.175 13.939,29.186 15.273,29.186 16.248,28.212 16.248,28.016 16.57,27.694 20.984,27.694 23.581,30.29 24.177,30.29 24.723,30.836 24.723,34.478 23.516,35.684 23.516,36.516 23.733,36.732 v1(23.733,36.841) ; v1(18.384,8.141) 18.459,8.066 18.459,7.579 18.88,7.158 R2.2@18.975,7.158
GPIO6/JTCK/SWCLK: CN1.15 R3.2 U1.26 | length 59.7
  Top Layer w0.2: v1(8.351,25.567) 7.675,24.891 7.675,20.621 13.037,15.26 14.79,15.26 16.757,13.293 16.757,12.264 19.845,9.177 19.845,8.299 v1(19.83,8.285) ; U1.26@23.711,35.378 23.756,35.423 23.756,35.728 24.066,36.037 v1(24.066,36.143)
  Internal 1 w0.2: v1(8.351,25.567) 9.055,26.271 10.814,26.271 12.934,24.151 21.027,24.151 23.004,26.128 23.004,35.859 23.288,36.143 v1(24.066,36.143)
  Bottom Layer w0.2: CN1.15@2.335,24.903 3.695,24.903 4.336,25.544 8.328,25.544 v1(8.351,25.567) ; v1(19.83,8.285) 19.83,8.203 20.211,7.821 R3.2@20.211,7.176
GPIO11: CN1.24 SB46.1 | length 14.6
  Top Layer w0.2: v1(10.022,19.256) 10.098,19.333 10.344,19.333 10.462,19.45 11.413,19.45 11.715,19.752 16.873,19.752 v1(18.225,18.4)
  Bottom Layer w0.2: CN1.24@6.399,19.823 6.543,19.679 9.596,19.679 10.019,19.256 v1(10.022,19.256) ; v1(18.225,18.4) 18.25,18.425 19.825,18.425 19.92,18.52 SB46.1@19.932,18.52
GPIO12: CN1.47 R8.2 SB44.1 | length 28.5
  Internal 1 w0.2: v1(16.324,3.325) 16.399,3.25 16.612,3.25 16.798,3.065 24.463,3.065 26.197,4.799 v1(26.197,6.989)
  Bottom Layer w0.2: CN1.47@2.335,4.583 2.421,4.497 4.178,4.497 4.711,3.965 7.867,3.965 7.933,3.898 SB44.1@8.629,3.898 8.629,3.883 8.867,3.646 8.867,3.444 9.013,3.298 16.297,3.298 v1(16.324,3.325) ; R8.2@25.31,7.158 26.042,7.158 26.197,7.003 v1(26.197,6.989)
GPIO13: CN1.26 SB9.1 | length 12.7
  Top Layer w0.2: v1(8.075,18.345) 8.165,18.345 9.729,16.781 v1(9.729,9.27)
  Bottom Layer w0.2: CN1.26@6.399,18.553 6.607,18.345 v1(8.075,18.345) ; v1(9.729,9.27) 10.35,8.649 10.35,8.551 10.464,8.437 SB9.1@10.464,8.425
GPIO14: CN1.29 SB30.1 | length 27.2
  Internal 1 w0.2: v1(4.3,16) 6.773,18.473 6.773,22.303 8.445,23.975 12.557,23.975 12.731,23.801 21.831,23.801 22.595,23.037 22.885,23.037 v1(22.962,22.96)
  Bottom Layer w0.2: CN1.29@2.335,16.013 2.348,16 v1(4.3,16) ; v1(22.962,22.96) SB30.1@23.568,22.96
GPIO15/OSC32_IN: CN1.33 SB37.2 | length 45.8
  Top Layer w0.2: v1(21.44,21.262) 21.511,21.19 21.511,19.002 21.148,18.64 21.148,14.991 v1(22.178,13.961)
  Internal 1 w0.2: v1(4.367,13.447) 4.361,13.44 4.361,12.747 6.027,11.08 19.297,11.08 v1(22.178,13.961)
  Bottom Layer w0.2: CN1.33@2.335,13.473 2.361,13.447 v1(4.367,13.447) ; v1(21.44,21.262) 21.44,21.322 22.192,22.074 22.192,24.97 23.422,26.2 24.25,26.2 24.302,26.252 24.322,26.252 24.849,26.779 24.849,26.799 25.028,26.978 25.769,26.978 28.713,29.921 28.713,31.091 28.454,31.35 28.335,31.35 28.073,31.613 SB37.2@28.073,32.407
GPIO16/OSC32_OUT: CN1.35 SB38.2 | length 44.8
  Top Layer w0.2: v1(20.252,21.273) 20.934,20.591 20.934,18.921 20.798,18.785 20.798,14.842 21.628,14.012 21.628,13.733 21.95,13.411 22.121,13.411 22.312,13.221 v1(22.42,13.221)
  Internal 1 w0.2: v1(4.332,11.705) 4.408,11.628 4.655,11.628 5.553,10.73 19.446,10.73 21.937,13.221 v1(22.42,13.221)
  Bottom Layer w0.2: CN1.35@2.335,12.203 3.982,12.203 4.354,11.831 4.332,11.809 v1(4.332,11.705) ; v1(20.252,21.273) 20.325,21.346 20.325,23.82 23.106,26.602 24.177,26.602 24.499,26.924 24.499,26.944 24.883,27.328 25.624,27.328 28.088,29.791 28.088,30.7 28.09,30.701 SB38.2@28.09,30.748
GPIO17: CN1.36 SB8.1 | length 4.6
  Bottom Layer w0.2: CN1.36@6.399,12.203 6.417,12.185 8.743,12.185 9.729,11.199 SB8.1@10.538,11.199 ; 10.451,11.401 10.465,11.386 10.515,11.386 10.526,11.376
GPIO18: CN2.45 SB18.1 | length 4.1
  Bottom Layer w0.2: SB18.1@32.547,5.853 CN2.45@36.625,5.853
GPIO19: CN2.15 SB23.1 | length 3.3
  Bottom Layer w0.2: SB23.1@33.332,24.903 CN2.15@36.625,24.903
GPIO20: CN1.38 SB16.1 | length 4.5
  Bottom Layer w0.2: CN1.38@6.399,10.933 6.432,10.9 8.218,10.9 9.293,9.825 SB16.1@10.476,9.825
GPIO21: CN2.21 SB17.1 | length 3.8
  Bottom Layer w0.2: 33.325,21.6 33.325,21.615 33.4,21.69 33.4,21.861 34.023,21.861 34.791,21.093 CN2.21@36.625,21.093
GPIO22: CN1.44 SB14.1 | length 4.2
  Bottom Layer w0.2: CN1.44@6.399,7.123 9.584,7.123 10.246,7.123 10.462,7.339
GPIO23: CN2.11 SB21.1 | length 3.3
  Bottom Layer w0.2: SB21.1@33.301,27.458 36.61,27.458 CN2.11@36.625,27.443
GPIO24: CN2.39 U1.4 | length 34.9
  Top Layer w0.2: U1.4@20.211,28.628 20.242,28.598 20.242,28.053 20.354,27.941 20.354,25.984 20.713,25.625 20.713,23.734 19.724,22.746 19.722,22.746 18.847,21.87 18.847,14.605 20.843,12.608 v1(22.943,12.608)
  Bottom Layer w0.2: v1(22.943,12.608) 24.705,12.608 27.728,9.585 36.547,9.585 CN2.39@36.625,9.663
GPIO25: CN2.42 SB7.1 | length 8.6
  Bottom Layer w0.2: SB7.1@32.525,7.339 32.533,7.347 32.592,7.347 32.595,7.35 33.644,7.35 34.041,7.747 38.105,7.747 38.751,8.393 CN2.42@40.689,8.393
GPIO26: CN1.42 SB45.1 | length 2.2
  Bottom Layer w0.2: CN1.42@6.399,8.393 8.322,8.393 8.535,8.606
GPIO27: CN2.35 SB12.1 | length 4.5
  Bottom Layer w0.2: SB12.1@32.525,12.5 32.525,12.495 32.595,12.425 34.203,12.425 34.425,12.203 CN2.35@36.625,12.203 CN2.35@36.403,12.425
GPIO28: CN2.7 SB22.2 | length 3.6
  Bottom Layer w0.2: SB22.2@33.414,30.79 33.428,30.79 33.463,30.825 34.21,30.825 35.045,29.99 36.618,29.99 CN2.7@36.625,29.983
GPIO29: CN2.23 SB48.1 | length 2.7
  Bottom Layer w0.2: SB48.1@33.323,20.678 34.126,19.875 35.545,19.875 CN2.23@35.625,19.794
GPIO30: CN2.10 SB13.2 | length 7.9
  Bottom Layer w0.2: SB13.2@33.377,28.774 33.6,28.774 34.28,28.095 38.126,28.095 38.718,28.687 40.663,28.687 CN2.10@40.689,28.713
GPIO31: CN2.13 SB10.2 | length 3.2
  Bottom Layer w0.2: SB10.2@33.413,26.173 SB10.2@33.425,26.173 33.452,26.201 36.597,26.201 CN2.13@36.625,26.173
